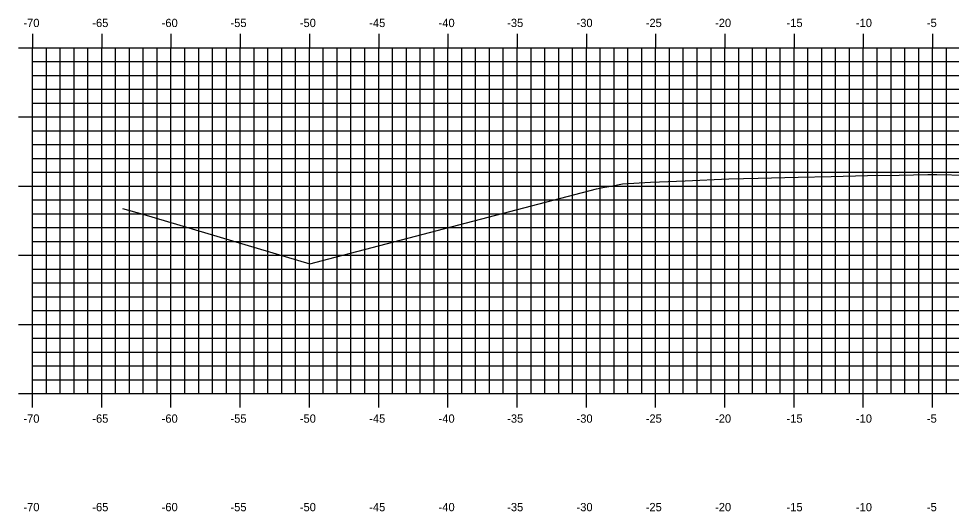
# Model space of a CAD drawing. Extents: x 1170543 to 1177585, y 609599 to 610623.
# Drawn here: x 1176542.9 to 1176610.3, y 610334.3 to 610369.9 of the extents above; entities that cross this region are included whole.
import ezdxf

# ---------------------------------------------------------------- set-up
doc = ezdxf.new("R2010")
doc.units = 0
for name, color, linetype in [('H_V ANNOTATION', 7, 'Continuous'), ('MAJOR', 7, 'Continuous'), ('MINOR', 7, 'Continuous'), ('S_Roadway_Centerline', 7, 'Continuous')]:
    doc.layers.add(name, color=color, linetype=linetype)

msp = doc.modelspace()

# ---------------------------------------------------------------- linework, layer by layer
at = {"layer": 'MAJOR'}
for p, q in [((1176543.898, 610368.803), (1176543.898, 610367.801)), ((1176548.898, 610368.803), (1176548.898, 610367.801)), ((1176553.898, 610368.803), (1176553.898, 610367.801)), ((1176558.898, 610368.803), (1176558.898, 610367.801)), ((1176563.898, 610368.803), (1176563.898, 610367.801)), ((1176568.898, 610368.803), (1176568.898, 610367.801)), ((1176573.898, 610368.803), (1176573.898, 610367.801)), ((1176578.898, 610368.803), (1176578.898, 610367.801)), ((1176583.898, 610368.803), (1176583.898, 610367.801)), ((1176588.898, 610368.803), (1176588.898, 610367.801)), ((1176593.898, 610368.803), (1176593.898, 610367.801)), ((1176598.898, 610368.803), (1176598.898, 610367.801)), ((1176603.898, 610368.803), (1176603.898, 610367.801)), ((1176608.898, 610368.803), (1176608.898, 610367.801)), ((1176542.896, 610367.801), (1176543.898, 610367.801)), ((1176543.898, 610367.801), (1176683.898, 610367.801)), ((1176543.898, 610342.801), (1176543.898, 610367.801)), ((1176543.898, 610342.801), (1176543.898, 610367.801)), ((1176543.898, 610367.801), (1176683.898, 610367.801)), ((1176548.898, 610342.801), (1176548.898, 610367.801)), ((1176553.898, 610342.801), (1176553.898, 610367.801)), ((1176558.898, 610342.801), (1176558.898, 610367.801)), ((1176563.898, 610342.801), (1176563.898, 610367.801)), ((1176568.898, 610342.801), (1176568.898, 610367.801)), ((1176573.898, 610342.801), (1176573.898, 610367.801)), ((1176578.898, 610342.801), (1176578.898, 610367.801)), ((1176583.898, 610342.801), (1176583.898, 610367.801)), ((1176588.898, 610342.801), (1176588.898, 610367.801)), ((1176593.898, 610342.801), (1176593.898, 610367.801)), ((1176598.898, 610342.801), (1176598.898, 610367.801)), ((1176603.898, 610342.801), (1176603.898, 610367.801)), ((1176608.898, 610342.801), (1176608.898, 610367.801)), ((1176542.896, 610362.801), (1176543.898, 610362.801)), ((1176543.898, 610362.801), (1176683.898, 610362.801)), ((1176542.896, 610357.801), (1176543.898, 610357.801)), ((1176543.898, 610357.801), (1176683.898, 610357.801)), ((1176542.896, 610352.801), (1176543.898, 610352.801)), ((1176543.898, 610352.801), (1176683.898, 610352.801)), ((1176542.896, 610347.801), (1176543.898, 610347.801)), ((1176543.898, 610347.801), (1176683.898, 610347.801)), ((1176542.896, 610342.801), (1176543.898, 610342.801)), ((1176543.898, 610342.801), (1176683.898, 610342.801)), ((1176543.898, 610342.801), (1176683.898, 610342.801)), ((1176543.898, 610341.799), (1176543.898, 610342.801)), ((1176548.898, 610341.799), (1176548.898, 610342.801)), ((1176553.898, 610341.799), (1176553.898, 610342.801)), ((1176558.898, 610341.799), (1176558.898, 610342.801)), ((1176563.898, 610341.799), (1176563.898, 610342.801)), ((1176568.898, 610341.799), (1176568.898, 610342.801)), ((1176573.898, 610341.799), (1176573.898, 610342.801)), ((1176578.898, 610341.799), (1176578.898, 610342.801)), ((1176583.898, 610341.799), (1176583.898, 610342.801)), ((1176588.898, 610341.799), (1176588.898, 610342.801)), ((1176593.898, 610341.799), (1176593.898, 610342.801)), ((1176598.898, 610341.799), (1176598.898, 610342.801)), ((1176603.898, 610341.799), (1176603.898, 610342.801)), ((1176608.898, 610341.799), (1176608.898, 610342.801))]:
    msp.add_line(p, q, dxfattribs=at)
at = {"layer": 'MINOR'}
for p, q in [((1176544.898, 610342.801), (1176544.898, 610367.801)), ((1176545.898, 610342.801), (1176545.898, 610367.801)), ((1176546.898, 610342.801), (1176546.898, 610367.801)), ((1176547.898, 610342.801), (1176547.898, 610367.801)), ((1176549.898, 610342.801), (1176549.898, 610367.801)), ((1176550.898, 610342.801), (1176550.898, 610367.801)), ((1176551.898, 610342.801), (1176551.898, 610367.801)), ((1176552.898, 610342.801), (1176552.898, 610367.801)), ((1176554.898, 610342.801), (1176554.898, 610367.801)), ((1176555.898, 610342.801), (1176555.898, 610367.801)), ((1176556.898, 610342.801), (1176556.898, 610367.801)), ((1176557.898, 610342.801), (1176557.898, 610367.801)), ((1176559.898, 610342.801), (1176559.898, 610367.801)), ((1176560.898, 610342.801), (1176560.898, 610367.801)), ((1176561.898, 610342.801), (1176561.898, 610367.801)), ((1176562.898, 610342.801), (1176562.898, 610367.801)), ((1176564.898, 610342.801), (1176564.898, 610367.801)), ((1176565.898, 610342.801), (1176565.898, 610367.801)), ((1176566.898, 610342.801), (1176566.898, 610367.801)), ((1176567.898, 610342.801), (1176567.898, 610367.801)), ((1176569.898, 610342.801), (1176569.898, 610367.801)), ((1176570.898, 610342.801), (1176570.898, 610367.801)), ((1176571.898, 610342.801), (1176571.898, 610367.801)), ((1176572.898, 610342.801), (1176572.898, 610367.801)), ((1176574.898, 610342.801), (1176574.898, 610367.801)), ((1176575.898, 610342.801), (1176575.898, 610367.801)), ((1176576.898, 610342.801), (1176576.898, 610367.801)), ((1176577.898, 610342.801), (1176577.898, 610367.801)), ((1176579.898, 610342.801), (1176579.898, 610367.801)), ((1176580.898, 610342.801), (1176580.898, 610367.801)), ((1176581.898, 610342.801), (1176581.898, 610367.801)), ((1176582.898, 610342.801), (1176582.898, 610367.801)), ((1176584.898, 610342.801), (1176584.898, 610367.801)), ((1176585.898, 610342.801), (1176585.898, 610367.801)), ((1176586.898, 610342.801), (1176586.898, 610367.801)), ((1176587.898, 610342.801), (1176587.898, 610367.801)), ((1176589.898, 610342.801), (1176589.898, 610367.801)), ((1176590.898, 610342.801), (1176590.898, 610367.801)), ((1176591.898, 610342.801), (1176591.898, 610367.801)), ((1176592.898, 610342.801), (1176592.898, 610367.801)), ((1176594.898, 610342.801), (1176594.898, 610367.801)), ((1176595.898, 610342.801), (1176595.898, 610367.801)), ((1176596.898, 610342.801), (1176596.898, 610367.801)), ((1176597.898, 610342.801), (1176597.898, 610367.801)), ((1176599.898, 610342.801), (1176599.898, 610367.801)), ((1176600.898, 610342.801), (1176600.898, 610367.801)), ((1176601.898, 610342.801), (1176601.898, 610367.801)), ((1176602.898, 610342.801), (1176602.898, 610367.801)), ((1176604.898, 610342.801), (1176604.898, 610367.801)), ((1176605.898, 610342.801), (1176605.898, 610367.801)), ((1176606.898, 610342.801), (1176606.898, 610367.801)), ((1176607.898, 610342.801), (1176607.898, 610367.801)), ((1176609.898, 610342.801), (1176609.898, 610367.801)), ((1176543.898, 610366.801), (1176683.898, 610366.801)), ((1176543.898, 610366.801), (1176544.9, 610366.801)), ((1176543.898, 610365.801), (1176683.898, 610365.801)), ((1176543.898, 610365.801), (1176544.9, 610365.801)), ((1176543.898, 610364.801), (1176683.898, 610364.801)), ((1176543.898, 610364.801), (1176544.9, 610364.801)), ((1176543.898, 610363.801), (1176683.898, 610363.801)), ((1176543.898, 610363.801), (1176544.9, 610363.801)), ((1176543.898, 610361.801), (1176683.898, 610361.801)), ((1176543.898, 610361.801), (1176544.9, 610361.801)), ((1176543.898, 610360.801), (1176683.898, 610360.801)), ((1176543.898, 610360.801), (1176544.9, 610360.801)), ((1176543.898, 610359.801), (1176683.898, 610359.801)), ((1176543.898, 610359.801), (1176544.9, 610359.801)), ((1176543.898, 610358.801), (1176683.898, 610358.801)), ((1176543.898, 610358.801), (1176544.9, 610358.801)), ((1176543.898, 610356.801), (1176683.898, 610356.801)), ((1176543.898, 610356.801), (1176544.9, 610356.801)), ((1176543.898, 610355.801), (1176683.898, 610355.801)), ((1176543.898, 610355.801), (1176544.9, 610355.801)), ((1176543.898, 610354.801), (1176683.898, 610354.801)), ((1176543.898, 610354.801), (1176544.9, 610354.801)), ((1176543.898, 610353.801), (1176683.898, 610353.801)), ((1176543.898, 610353.801), (1176544.9, 610353.801)), ((1176543.898, 610351.801), (1176683.898, 610351.801)), ((1176543.898, 610351.801), (1176544.9, 610351.801)), ((1176543.898, 610350.801), (1176683.898, 610350.801)), ((1176543.898, 610350.801), (1176544.9, 610350.801)), ((1176543.898, 610349.801), (1176683.898, 610349.801)), ((1176543.898, 610349.801), (1176544.9, 610349.801)), ((1176543.898, 610348.801), (1176683.898, 610348.801)), ((1176543.898, 610348.801), (1176544.9, 610348.801)), ((1176543.898, 610346.801), (1176683.898, 610346.801)), ((1176543.898, 610346.801), (1176544.9, 610346.801)), ((1176543.898, 610345.801), (1176683.898, 610345.801)), ((1176543.898, 610345.801), (1176544.9, 610345.801)), ((1176543.898, 610344.801), (1176683.898, 610344.801)), ((1176543.898, 610344.801), (1176544.9, 610344.801)), ((1176543.898, 610343.801), (1176683.898, 610343.801)), ((1176543.898, 610343.801), (1176544.9, 610343.801))]:
    msp.add_line(p, q, dxfattribs=at)
at = {"layer": 'S_Roadway_Centerline'}
msp.add_lwpolyline([(1176550.398, 610356.197), (1176551.869, 610355.767), (1176563.916, 610352.178), (1176565.302, 610352.546), (1176584.623, 610357.603), (1176585.198, 610357.717), (1176585.676, 610357.795), (1176586.504, 610357.963), (1176588.524, 610358.079), (1176589.187, 610358.112), (1176591.022, 610358.191), (1176594.194, 610358.328), (1176596.297, 610358.382), (1176599.2, 610358.457), (1176601.571, 610358.508), (1176604.206, 610358.563), (1176606.485, 610358.607), (1176608.566, 610358.646), (1176608.924, 610358.641), (1176609.213, 610358.637), (1176611.353, 610358.595)], dxfattribs=at)

# ---------------------------------------------------------------- texts
at = {"layer": 'H_V ANNOTATION'}
for s, p in [('-70', (1176543.24, 610369.301)), ('-65', (1176548.216, 610369.301)), ('-60', (1176553.224, 610369.301)), ('-55', (1176558.194, 610369.301)), ('-50', (1176563.202, 610369.301)), ('-45', (1176568.216, 610369.301)), ('-40', (1176573.224, 610369.301)), ('-35', (1176578.178, 610369.301)), ('-30', (1176583.186, 610369.301)), ('-25', (1176588.183, 610369.301)), ('-20', (1176593.191, 610369.301)), ('-15', (1176598.355, 610369.301)), ('-10', (1176603.363, 610369.301)), ('-5', (1176608.489, 610369.301)), ('-70', (1176543.24, 610340.701)), ('-65', (1176548.216, 610340.701)), ('-60', (1176553.224, 610340.701)), ('-50', (1176563.202, 610340.701)), ('-40', (1176573.224, 610340.701)), ('-35', (1176578.178, 610340.701)), ('-30', (1176583.186, 610340.701)), ('-25', (1176588.183, 610340.701)), ('-20', (1176593.191, 610340.701)), ('-10', (1176603.363, 610340.701)), ('-55', (1176558.194, 610340.701)), ('-45', (1176568.216, 610340.701)), ('-15', (1176598.355, 610340.701)), ('-5', (1176608.489, 610340.701)), ('-70', (1176543.24, 610334.301)), ('-65', (1176548.216, 610334.301)), ('-60', (1176553.224, 610334.301)), ('-55', (1176558.194, 610334.301)), ('-50', (1176563.202, 610334.301)), ('-45', (1176568.216, 610334.301)), ('-40', (1176573.224, 610334.301)), ('-35', (1176578.178, 610334.301)), ('-30', (1176583.186, 610334.301)), ('-25', (1176588.183, 610334.301)), ('-20', (1176593.191, 610334.301)), ('-15', (1176598.355, 610334.301)), ('-10', (1176603.363, 610334.301)), ('-5', (1176608.489, 610334.301))]:
    msp.add_text(s, height=0.6, dxfattribs=at).set_placement(p)

doc.saveas('drawing.dxf')
